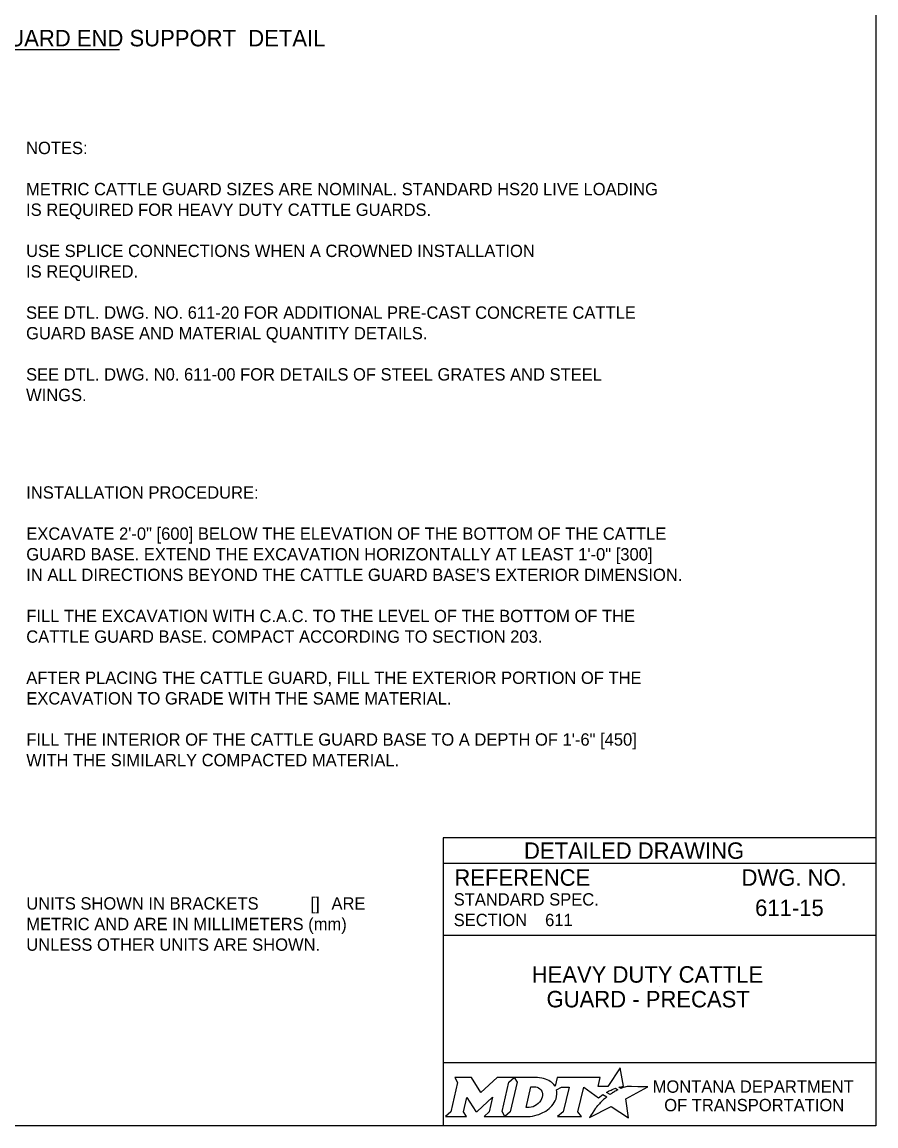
# Model space of a CAD drawing. Extents: x 49991.4 to 50021, y 49987.6 to 50011.4.
# Drawn here: x 50012.61 to 50016.75, y 49987.8 to 49993.16 of the extents above; entities that cross this region are included whole.
import ezdxf

# ---------------------------------------------------------------- set-up
doc = ezdxf.new("R2010")
doc.units = 0
for name, color, linetype in [('Default', 7, 'Continuous'), ('Level 1', 7, 'Continuous'), ('Level 2', 7, 'Continuous'), ('Level 5', 7, 'Continuous')]:
    doc.layers.add(name, color=color, linetype=linetype)

msp = doc.modelspace()

# ---------------------------------------------------------------- linework, layer by layer
at = {"layer": 'Default'}
for points in [[(50015.5126, 49987.9811), (50015.5023, 49987.9867), (50015.5139, 49987.9895), (50015.5255, 49987.9915), (50015.5081, 49988.0816), (50015.4486, 49987.9903), (50015.4013, 49987.9896), (50015.4116, 49988.0337), (50015.2024, 49988.0338), (50015.1923, 49987.9913), (50015.1865, 49987.9996)], [(50014.7056, 49988.0338), (50014.7197, 49988.0104), (50014.6862, 49987.8671), (50014.6605, 49987.8446), (50014.7621, 49987.8446), (50014.7486, 49987.8674), (50014.7648, 49987.9375), (50014.8085, 49987.8685), (50014.8138, 49987.8685), (50014.8889, 49987.938), (50014.8725, 49987.8669), (50014.8478, 49987.8449), (50014.9494, 49987.8449), (50014.9356, 49987.8682), (50014.9688, 49988.0106)], [(50014.9688, 49988.0106), (50014.9941, 49988.0338), (50014.9117, 49988.0338), (50014.8321, 49987.9608), (50014.7876, 49988.0335), (50014.7056, 49988.0338)], [(50015.1077, 49988.0338), (50014.9941, 49988.0338), (50015.0088, 49988.0109), (50014.9749, 49987.8671), (50014.9494, 49987.8449), (50015.06, 49987.8449)], [(50015.1317, 49987.9471), (50015.1305, 49987.939), (50015.1273, 49987.9297), (50015.1231, 49987.9215), (50015.1175, 49987.914), (50015.111, 49987.9071), (50015.1031, 49987.9008), (50015.0948, 49987.8961), (50015.0857, 49987.8922), (50015.0766, 49987.8899), (50015.0674, 49987.889), (50015.0515, 49987.889), (50015.0751, 49987.989), (50015.0911, 49987.989), (50015.0987, 49987.9884), (50015.1063, 49987.9865), (50015.1129, 49987.9835), (50015.119, 49987.9793), (50015.1238, 49987.9743), (50015.1275, 49987.9683), (50015.1302, 49987.9621), (50015.1318, 49987.9547), (50015.1318, 49987.9517), (50015.1317, 49987.9471)], [(50015.1991, 49987.9747), (50015.2237, 49987.9878), (50015.2606, 49987.9878), (50015.232, 49987.8673), (50015.2045, 49987.8446), (50015.3207, 49987.8446), (50015.3037, 49987.8675), (50015.3319, 49987.9877), (50015.4032, 49987.936), (50015.4243, 49987.9511), (50015.444, 49987.9402)], [(50015.3882, 49987.8843), (50015.3729, 49987.8599), (50015.3682, 49987.8524), (50015.3624, 49987.8438), (50015.3601, 49987.8395), (50015.4654, 49987.8926), (50015.5493, 49987.8375), (50015.5362, 49987.9302), (50015.6431, 49987.9886), (50015.5938, 49987.9894), (50015.5637, 49987.9898), (50015.5429, 49987.9901), (50015.5361, 49987.9886), (50015.5312, 49987.9874), (50015.5228, 49987.9851), (50015.5126, 49987.9811)], [(50015.4622, 49987.9535), (50015.4598, 49987.9518), (50015.4415, 49987.9614), (50015.4518, 49987.9671), (50015.4559, 49987.9693), (50015.4645, 49987.9733), (50015.4702, 49987.9759), (50015.4781, 49987.9789), (50015.4854, 49987.9816), (50015.4972, 49987.9742), (50015.4932, 49987.9721), (50015.4886, 49987.9696), (50015.4844, 49987.9674), (50015.4794, 49987.9645), (50015.4775, 49987.9634), (50015.4748, 49987.9618), (50015.4723, 49987.9604), (50015.47, 49987.9588), (50015.4674, 49987.957), (50015.4647, 49987.9552), (50015.4622, 49987.9535)], [(50015.4021, 49987.9004), (50015.4021, 49987.9004)], [(50015.1057, 49987.8522), (50015.1141, 49987.8548), (50015.1271, 49987.8602), (50015.1475, 49987.8712)]]:
    msp.add_lwpolyline(points, dxfattribs=at)
for centre, radius, start, end in [((50015.1308, 49987.9554), 0.0709, 339.5329, 15.8582), ((50015.0868, 49987.9727), 0.1183, 300.9103, 339.1383)]:
    msp.add_arc(centre, radius, start, end, dxfattribs=at)
for centre, major_axis, ratio, start_param, end_param in [((50015.1056, 49987.9864), (0.0834, -0.0037), 0.568097, 0.61298, 1.570796), ((50015.1612, 49987.9937), (0.0361, -0.0295), 0.469099, 1.225588, 1.570796), ((50015.4329, 49987.9305), (-0.0112, -0.0097), 0.021651, 3.157348, 6.283185), ((50015.3952, 49987.8923), (-0.00694, -0.00806), 0.008222, 0, 3.137361), ((50015.4119, 49987.9106), (-0.0098, -0.0102), 0.016458, 3.141593, 6.279097), ((50015.0603, 49987.9932), (0, 0.1484), 0.987302, 3.139398, 3.456847)]:
    msp.add_ellipse(centre, major_axis=major_axis, ratio=ratio, start_param=start_param, end_param=end_param, dxfattribs=at)
at = {"layer": 'Level 1'}
msp.add_lwpolyline([(49999.3835, 49998.9992), (50016.7501, 49998.9992), (50016.7501, 49987.7988), (49999.3835, 49987.7988)], close=True, dxfattribs=at)
at = {"layer": 'Level 2'}
msp.add_line((50011.407, 49993.0272), (50013.0786, 49993.0272), dxfattribs=at)
at = {"layer": 'Level 5'}
for p, q in [((50016.7501, 49989.1988), (50014.6501, 49989.1988)), ((50014.6501, 49989.1988), (50014.6501, 49987.7988)), ((50016.7501, 49989.0738), (50014.6501, 49989.0738)), ((50016.3862, 49988.8587), (50016.3862, 49988.8587)), ((50015.1444, 49988.7993), (50015.1444, 49988.7993)), ((50016.7501, 49988.7238), (50014.6501, 49988.7238)), ((50015.7001, 49988.4747), (50015.7001, 49988.4747)), ((50016.7501, 49988.1057), (50014.6501, 49988.1057))]:
    msp.add_line(p, q, dxfattribs=at)

# ---------------------------------------------------------------- texts
at = {"layer": 'Default'}
for s, p in [('MONTANA DEPARTMENT', (50015.6663, 49987.96)), ('OF TRANSPORTATION', (50015.7225, 49987.87))]:
    msp.add_text(s, height=0.06, rotation=360, dxfattribs=at).set_placement(p)
at = {"layer": 'Level 2'}
for s, height, p in [("16' [4.8 m] CATTLE GUARD END SUPPORT  DETAIL", 0.08, (50011.4892, 49993.0432)), ('NOTES:', 0.06, (50012.6245, 49992.5198)), ('METRIC CATTLE GUARD SIZES ARE NOMINAL. STANDARD HS20 LIVE LOADING', 0.06, (50012.6245, 49992.3198)), ('IS REQUIRED FOR HEAVY DUTY CATTLE GUARDS.', 0.06, (50012.6245, 49992.2198)), ('USE SPLICE CONNECTIONS WHEN A CROWNED INSTALLATION', 0.06, (50012.6245, 49992.0198)), ('IS REQUIRED.', 0.06, (50012.6245, 49991.9198)), ('SEE DTL. DWG. NO. 611-20 FOR ADDITIONAL PRE-CAST CONCRETE CATTLE', 0.06, (50012.6245, 49991.7198)), ('GUARD BASE AND MATERIAL QUANTITY DETAILS.', 0.06, (50012.6245, 49991.6198)), ('SEE DTL. DWG. N0. 611-00 FOR DETAILS OF STEEL GRATES AND STEEL', 0.06, (50012.6245, 49991.4198)), ('WINGS.      ', 0.06, (50012.6245, 49991.3198)), ('INSTALLATION PROCEDURE:', 0.06, (50012.6255, 49990.846)), ('EXCAVATE 2\'-0" [600] BELOW THE ELEVATION OF THE BOTTOM OF THE CATTLE', 0.06, (50012.6255, 49990.646)), ('GUARD BASE. EXTEND THE EXCAVATION HORIZONTALLY AT LEAST 1\'-0" [300]', 0.06, (50012.6255, 49990.546)), ("IN ALL DIRECTIONS BEYOND THE CATTLE GUARD BASE'S EXTERIOR DIMENSION.", 0.06, (50012.6255, 49990.446)), ('FILL THE EXCAVATION WITH C.A.C. TO THE LEVEL OF THE BOTTOM OF THE', 0.06, (50012.6255, 49990.246)), ('CATTLE GUARD BASE. COMPACT ACCORDING TO SECTION 203.  ', 0.06, (50012.6255, 49990.146)), ('AFTER PLACING THE CATTLE GUARD, FILL THE EXTERIOR PORTION OF THE', 0.06, (50012.6255, 49989.946)), ('EXCAVATION TO GRADE WITH THE SAME MATERIAL.  ', 0.06, (50012.6255, 49989.846)), ('FILL THE INTERIOR OF THE CATTLE GUARD BASE TO A DEPTH OF 1\'-6" [450] ', 0.06, (50012.6255, 49989.646)), ('WITH THE SIMILARLY COMPACTED MATERIAL.', 0.06, (50012.6255, 49989.546)), ('UNITS SHOWN IN BRACKETS ', 0.06, (50012.6255, 49988.8497)), ('[]', 0.06, (50014.0055, 49988.8497)), (' ARE ', 0.06, (50014.0849, 49988.8497)), ('611-15', 0.08, (50016.1636, 49988.8187)), ('METRIC AND ARE IN MILLIMETERS (mm) ', 0.06, (50012.6255, 49988.7497)), ('611', 0.06, (50015.1444, 49988.7693)), ('UNLESS OTHER UNITS ARE SHOWN.', 0.06, (50012.6255, 49988.6497)), ('HEAVY DUTY CATTLE', 0.08, (50015.0791, 49988.4947)), ('GUARD - PRECAST', 0.08, (50015.1512, 49988.3747))]:
    msp.add_text(s, height=height, dxfattribs=at).set_placement(p)
at = {"layer": 'Level 5'}
for s, height, p in [('DETAILED DRAWING', 0.0799, (50015.0418, 49989.0963)), ('REFERENCE', 0.08, (50014.7037, 49988.9654)), ('DWG. NO.', 0.08, (50016.0979, 49988.9654)), ('STANDARD SPEC.', 0.06, (50014.7004, 49988.8694)), ('SECTION', 0.06, (50014.7004, 49988.7694))]:
    msp.add_text(s, height=height, dxfattribs=at).set_placement(p)

doc.saveas('drawing.dxf')
